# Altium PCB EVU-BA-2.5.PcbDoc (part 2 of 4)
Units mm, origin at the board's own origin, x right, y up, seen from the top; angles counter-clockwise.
Board outline 80 x 82.5 mm, 4 copper layers (Top Layer, Int1, Int2, Bottom Layer), stack 1.49 mm thick; 257 components, 201 nets, 889 pads, 696 vias.
Unrouted connection lines stored in the file: 1.
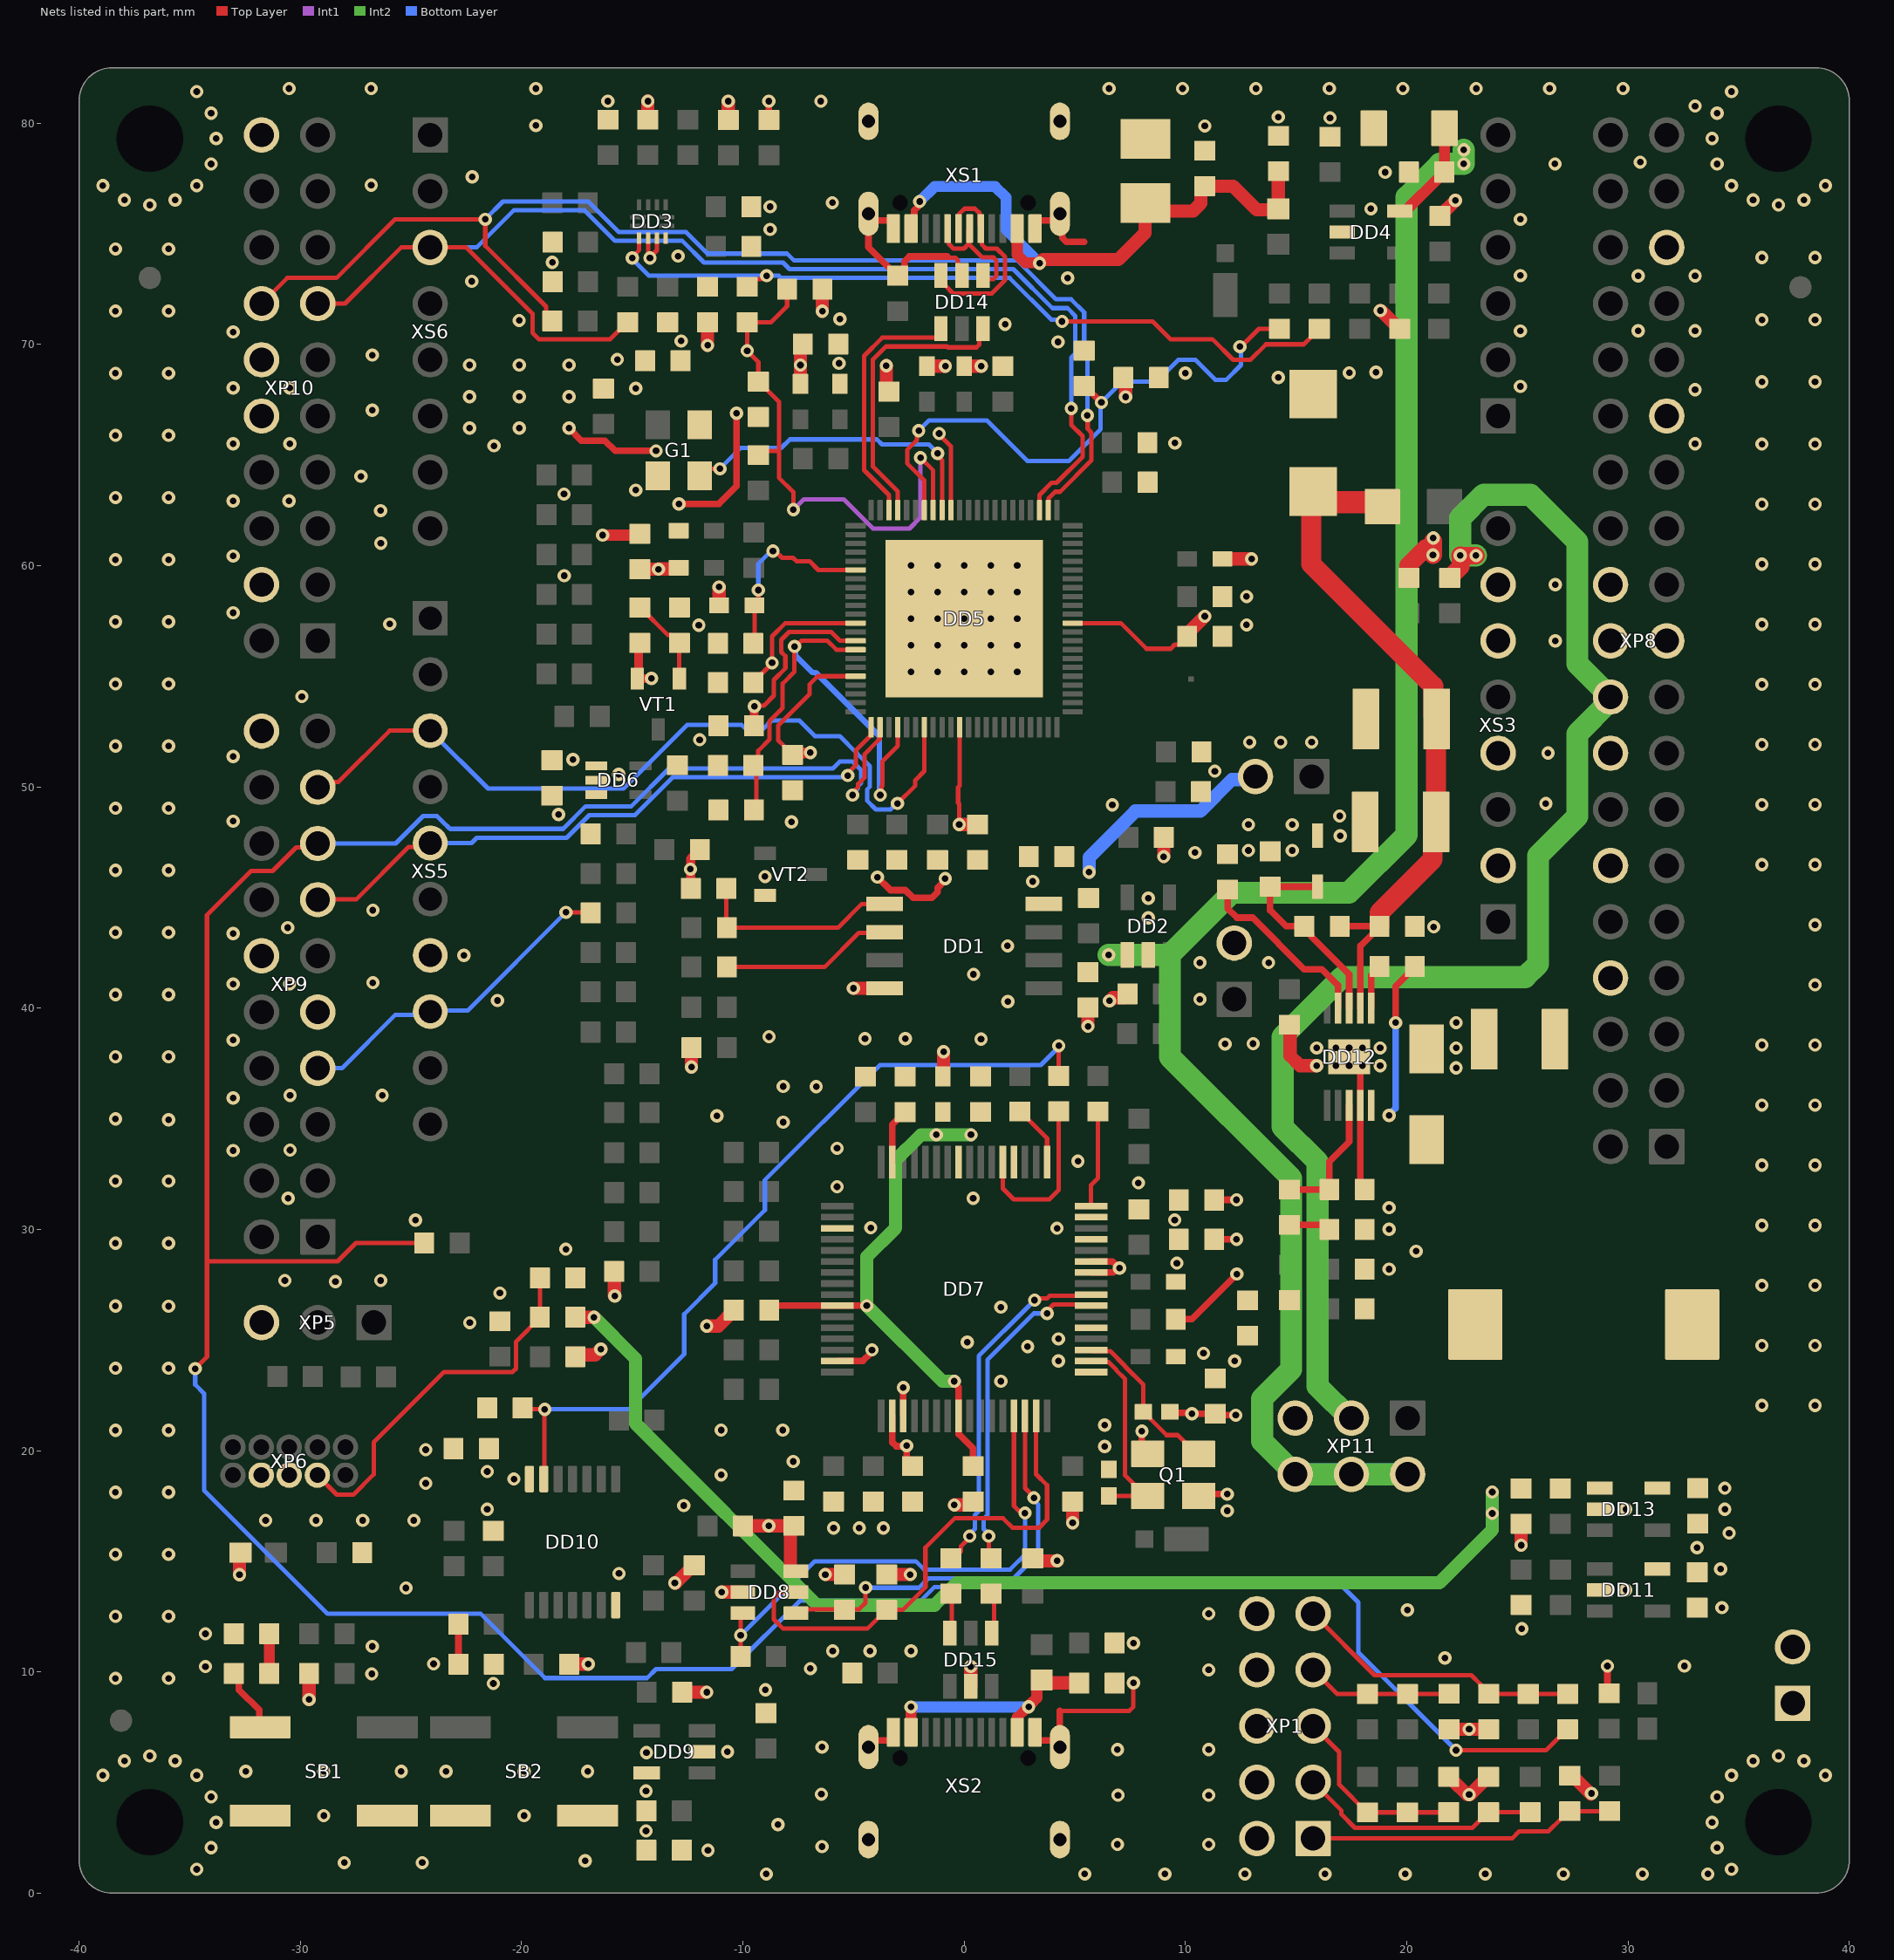
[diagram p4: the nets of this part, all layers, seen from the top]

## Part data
C1 C3 C7 C9 C10 C11 C12 C14 C15 C16 C17 C18 C19 C20 C21 C22 C23 C24 C25 C26 C29 C32 C33 C34 C35 C36 C37 C39 C41 C45 C46 C47 C48 C49 C50 C51 C52 C53 C54 C55 C57 C59 C60 C61 C62 C65 C67 C68 C75: "0603 X7R 0,1 uF ±10% 50V", Manufacturer="\"Kemet\"", Power_Voltage=50V, Tolerance=±10%, Value Ru="0,1 мкФ"
C2 C5 C6 C8 C27 C28 C30 C31 C40 C66 C69 C73 C74: "0603 X7R 1,0 uF±10% 16V", Manufacturer="\"Murata\"", Power_Voltage=16V, Tolerance=±10%, Value Ru="1,0 мкФ"
C4: "10 uF±20% 20V, Tantal capacitor, Type B", Manufacturer="\"Vishay\"", Power_Voltage=20V, Tolerance=±20%, Value Ru=10мкФ
C13: "1206 X7R 10 uF±10% 25V", Manufacturer="\"Murata\"", Power_Voltage=25V, Tolerance=±10%, Value Ru="10 мкФ"
C38: "0603 X7R 470 nF±10% 25V", Manufacturer="\"Murata\"", Power_Voltage=25V, Tolerance=±10%, Value Ru="0,47 мкФ"
C42 C43: "0402 COG 15 pF±5% 50V", Manufacturer="\"Murata\"", Power_Voltage=50V, Tolerance=±5%, Value Ru="15 пФ"
C44 C56 C58: "0603 X5R 4,7 uF ±10% 6,3V", Manufacturer="\"Murata\"", Power_Voltage=6,3V, Tolerance=±10%, Value Ru="4.7 мкФ"
C63 C64: "1210 X7R 2,2 uF±10% 100V", Manufacturer="\"Murata\"", Power_Voltage=100V, Tolerance=±10%, Value Ru="2,2 мкФ"
C70: "0603 X7R 33 nF±10% 50V", Manufacturer="\"Murata\"", Power_Voltage=50V, Tolerance=±10%, Value Ru="33000 пФ"
C71: "0603 X7R 15 pF±10% 16V", Manufacturer="\"Kemet\"", ManufacturerPartNumber=C0603C100K4RAC, Power_Voltage=16V, Tolerance=±10%, Value Ru="15 пФ"
C72: "1210 X7R 47 uF±20% 10V", Manufacturer="\"Murata\"", Power_Voltage=10V, Tolerance=±20%, Value Ru="47 мкФ"
D1: library part SMBJ48A-TR, "TVS Diode (Uni-directional)", Manufacturer="\"STMicroelectronics\"", Manufacturer_Name=STMicroelectronics, Mouser Part Number=511-SMBJ48A-TR, Power_Voltage="Vrm 48V, Irm 0.2A"
D2: "Zener Diode Vstab=4.7V, Iforvard=100mA, SOD-323, 0.55W", Manufacturer="\"Nexperia\"", Mouser Part Number=N/A
D3: "Schottky Diode  60V 3.0A", Arrow Part Number=B360A-E3/61T, Manufacturer="\"Vishay\"", Mouser Part Number=625-B360A-E3/61T
D6 D7: "Schottky Diod", Manufacturer="\"Vishay\""
DD1: "NOR Flash Serial (SPI, Dual SPI, Quad SPI) 3V/3.3V 128M-bit 128M", Arrow Part Number="MT25QL128ABA1ESE-0SIT TR", Manufacturer="\"Micron\"", Mouser Part Number=340-224871-REEL
DD2 DD11 DD13: "LDO voltage regulator Vout -3.3V, Iout - 0.6A max, Vout accuracy ±1.5%", Manufacturer="\"Diodes\"", Manufacturer_Name="Diodes Incorporated", Mouser Part Number=621-AP2112K-3.3TRG1
DD3: "USB Type-C Logic & Port Control", Manufacturer="\"Texas Instruments\"", Mouser Part Number=595-TUSB320RWBR
DD4: "Power switch, USB switch, 1.5A", Manufacturer="\"Diodes Incorporated\"", Mouser Part Number=621-AP2191WG-7
DD5: "Microcontroller BE-U1000", Manufacturer="\"Baikal Electronics\"", Package=None
DD6: "V-Ref Adjustable 0.2V to 18V 15mA", Manufacturer="\"Diodes Incorporated\"", Mouser Part Number=522-ZXRE160H5TA
DD7: "USB-UART/FIFO", Manufacturer="\"FTDI Chip\"", Mouser Part Number=895-FT2232HL
DD8: "EEPROM, 2KBIT, SERIAL, 2MHz", Arrow Part Number=93LC56BT-E/OT, Manufacturer="\"Microchip\"", Mouser Part Number=579-93LC56BT-E/OT
DD9: "Supervisor Integrated Circuit", Manufacturer="\"Texas Instruments\""
DD10: "Quadruple 2-Input Positive-AND Gates, PW0014A, LARGE T&R", F @ Nom Voltage(Max)(Mhz)=100, Generic Part Number=SN74AC08, ICC @ Nom Voltage(Max)(mA)=0.02, Manufacturer="\"Texas Instruments\"", Operating Temperature Range(C)="-40 to 85", Rating=Catalog, tpd @ Nom Voltage(Max)(ns)=10,8.5, Voltage(Nom)(V)=3.3,5
DD12: "DC-DC STEP DOWN Converter 1.5-A, 60V", Manufacturer="\"Texas Instruments\"", Mouser Part Number=595-TPS54160DGQ
DD14 DD15: "Very low capacitance ESD protector", Manufacturer="\"STMicroelectronics\""
FU1: "Fuse SMD 1,5A 63V", Manufacturer="\"Littelfuse\""
G1: "3.3V ±10ppm 5mA ±20ppm CMOS 25MHz  Oscillator", Manufacturer="\"YXC\""
L1 L10: "330 Ohms/100 MHz 1,5A 0,07 Ohms", Manufacturer="\"Murata\"", Value Ru="330 Ом/100MГц 1,5А 0,07 Ом"
L2 L3 L4 L5 L6 L7 L8 L9 L11 L12 L13: "470 Ohms/100MHz 1A 0,2 Ohms", Manufacturer="\"Murata\"", Value Ru="470 Ом/100MГц 1А 0,2 Ом"
L14: "33 uH±30% 2.75A 65mOhm SMD", Manufacturer="\"Sumida\"", Power_Voltage="2,4 A", Value Eng=33uH
LD1: "0603 LED Diod SMD Green", Manufacturer="\"Kingbright\""
LD2: "0603 LED Diod SMD White", Manufacturer="\"Kingbright\""
Q1: "Quartz Crystal 12MHz", Manufacturer="\"YXC\"", Value Ru="12,000 МГц"
R1 R78: "0603 100 Ohm±5% 0,1W", Manufacturer="\"Bourns\"", Power_Voltage=0,1W, Tolerance=±5%, Value Ru="100 Ом"
R2 R4 R6 R9 R10 R11 R12 R14 R17 R30 R32 R35 R38 R59 R62 R63 R80 R81 R82 R86 R107 R108 R112: "0603 10 kOhm±5% 0,1W", Manufacturer="\"Bourns\"", Power_Voltage=0,1W, Tolerance=±5%, Value Ru="10 кОм"
R3 R5 R7 R25 R26 R27 R28 R33 R72 R73 R74 R75 R76: "0603 22 Ohm ±5% 0.1W", Manufacturer="\"Bourns\"", Power_Voltage="0,1 Вт", Tolerance=±5%, Value Ru="22 Ом"
R8 R22 R23 R24 R34 R36 R37 R43 R44 R46 R47 R48 R49 R50 R51 R53 R56 R64 R65 R66 R67 R68 R69 R70 R71 R77 R79 R83 R84 R85 R90 R96 R98 R99 R100 R101 R102 R104 R105 R106 R114 R115 R116 R118 R119: "0603 0 Ohm 0,1W", Manufacturer="\"Bourns\"", Value Ru="0 Ом"
R13 R15 R109 R110: "0603 5,1 kOhm±5% 0,1W", Manufacturer="\"Bourns\"", ManufacturerPartNumber=CR0603-JW-682-E, Power_Voltage="0,1 Вт", Tolerance=±5%, Value Eng=5K1
R16: "0603 887 kOhm ±1% 0,1W", Manufacturer="\"Bourns\"", Power_Voltage="0,1 Вт", Tolerance=±1%, Value Ru="887 кОм"
R18 R19 R20 R21 R42 R111 R113: "0603 100 kOhm±5% 0.1W", Manufacturer="\"Bourns\"", Power_Voltage="0,1 Вт", Tolerance=±5%, Value Ru="100 кОм"
R29 R31: "0603 4,7 kOhm±5% 0.1W", Manufacturer="\"Bourns\"", Power_Voltage="0,1 Вт", Tolerance=±5%, Value Ru="4,7 кОм"
R39 R40 R41: "0603 200 kOhm±5% 0.1W", Manufacturer="\"Bourns\"", Power_Voltage="0,1 Вт", Tolerance=±5%, Value Ru="200 кОм"
R45 R52 R103 R117: "0603 1 kOhm±5% 0,1W", Manufacturer="\"Bourns\"", Power_Voltage="0,1 Вт", Tolerance=±5%, Value Eng=1K
R54: "0603 15 kOhm ±1% 0,1W", Manufacturer="\"Bourns\"", Power_Voltage="0,1 Вт", Tolerance=±1%, Value Ru="15 кОм"
R55 R94 R95: "0603 10 kOhm±1% 0,1W", Manufacturer="\"Bourns\"", Power_Voltage="0,1 Вт", Tolerance=±1%, Value Ru="10 кОм"
R57 R58: "0603 10 Ohm±5% 0.1W", Manufacturer="\"Bourns\"", Power_Voltage=0,1W, Tolerance=±5%, Value Ru="10 Ом"
R60 R97: "0603 2 kOhm±5% 0.1W", Manufacturer="\"Bourns\"", Power_Voltage="0,1 Вт", Tolerance=±5%, Value Ru="2 кОм"
R61: "0603 12 kOhm±1% 0,1W", Manufacturer="\"Bourns\"", ManufacturerPartNumber=CR0603-JW-123-E, Power_Voltage="0,1 Вт", Tolerance=±1%, Value Ru="12 кОм"
R87: "0603 330 Ohm ±5% 0.1W", Manufacturer="\"Bourns\"", Power_Voltage="0,1 Вт", Tolerance=±5%, Value Ru="330 Ом"
R88 R91: "0603 154 kOhm±1% 0,1W", Manufacturer="\"Bourns\"", Power_Voltage="0,1 Вт", Tolerance=±1%, Value Ru="154 кОм"
R89: "0603 22,1 kOhm±1% 0,1W", Manufacturer="\"Bourns\"", Power_Voltage="0,1 Вт", Tolerance=±1%, Value Ru="22,1 кОм"
R92: "0603 88,7 kOhm±1% 0,1W", Manufacturer="\"Bourns\"", Power_Voltage=0,1W, Tolerance=±1%, Value Ru="88,7 кОм"
R93: "0603 53,6 kOhm ±1% 0,1W", Manufacturer="\"Bourns\"", Power_Voltage=0,1W, Tolerance=±1%, Value Ru="53,6 кОм"
SB1 SB2: "Surface-mounting Sealed Tactile Switch", Manufacturer="\"Omron Corporation\"", ManufacturerPartNumber=B3SL-1022P
VT1: "P-MOSFET 50V 130mA SOT-23-3", Manufacturer="\"NXP Semiconductors\""
VT2: "N-MOSFET 50V 200mA SOT-23-3", Manufacturer="\"Fairchild Semiconductor\""
XP1: "Connector 2.54 pitch, 2 rows, 8.54 height, 5 pins per row", Manufacturer="\"Connfly\"", ManufacturerPartNumber=DS1021-2x5
XP2 XP3 XP7: "Connector 2.54 pitch, 1 row, 8.54 height, 2 pins per row", Manufacturer="\"Connfly\""
XP5: "Connector 2.54 pitch, 1 row, 8.54 height, 3 pins per row", Manufacturer="\"Connfly\""
XP6: "Connector 1.27 pitch, 2 rows, 5 pins per row", Manufacturer="\"Samtec\"", Manufacturer_Name=SAMTEC, Mouser Part Number=200-FTSH10501FDK
XP8: "Connector 2.54 pitch, 2 rows, 18.54 height, 19 pins per row", Manufacturer="\"Samtec\""
XP9 XP10: "Connector 2.54 pitch, 2 rows, 18.54 height, 10 pins per row", Manufacturer="\"Samtec\""
XP11: "Connector 2.54 pitch, 2 rows, 8.54 height, 3 pins per row", Manufacturer="\"Connfly\""
XS1 XS2: "USB TYPE-C 5A 16P Female SMD USB Connectors", Manufacturer="\"HRO\"", Package=None
XS3 XS6: "Connector 2.54 pitch, 1 row, 8.54 height, 8 pins per row", Manufacturer="\"Connfly\"", ManufacturerPartNumber="DS-1023-1x8 (PBS-8)"
XS4: "Connector 2.54 pitch, 1 row, 8.54 height, 6 pins per row", Manufacturer="\"Connfly\"", ManufacturerPartNumber=DS1023-1x6S21(PBS-6)
XS5: "Connector 2.54 pitch, 1 row, 8.54 height, 10 pins per row", Manufacturer="\"Connfly\"", ManufacturerPartNumber="DS1023-1X10S21 (PBS-10)"

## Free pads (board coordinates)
  round 1.6 hole 3 paste-2539.97 mask+1: 3(-36.8,3.2) 3(-36.8,79.3) 3(36.8,79.3) 3(36.8,3.2)

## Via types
v1: diameter 0.6, hole 0.3, Top Layer to Bottom Layer, tented both sides, 670 vias
v2: diameter 0.6, hole 0.3, Top Layer to Bottom Layer, tented bottom, 26 vias

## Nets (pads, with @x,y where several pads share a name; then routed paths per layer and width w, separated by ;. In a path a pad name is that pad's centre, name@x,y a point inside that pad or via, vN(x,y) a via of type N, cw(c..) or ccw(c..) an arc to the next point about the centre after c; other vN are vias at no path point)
1V7: C31.1 C37.2 DD5.37 DD5.48 | length 22.7
  Top Layer w0.2: C31.1@-9.528,50.975 C31.1@-9.392,50.975 ; C37.2@-9.392,49.23 C31.1@-9.392,50.975 ; v1(-7.667,56.345) -7.667,55.202 -8.2,54.669 -8.2,53.566 -8.8,52.966 -8.8,52.137 -9.304,51.633 -9.304,51.063 C31.1@-9.392,50.975 ; v1@-7.558,56.4 -7.358,56.6 -6.173,56.6 -5.773,56.2 DD5.37@-4.905,56.2 ; v1(-3.79,49.628) -3.734,49.685 -3.734,50.02 -3.695,50.058 -3.695,51.153 -3.4,51.448 -3,51.848 DD5.48@-3,52.695
  Bottom Layer w0.25: v1(-7.667,56.345) -7.625,56.303 -7.625,55.933 -6.859,55.167 -6.711,55.167 -3.832,52.288 -3.832,49.669 v1(-3.79,49.628)
3V3: C7.1 C10.1 C23.2 C25.2 C29.2 C61.2 C62.2 C74.2 DD3.12 DD5.36 DD6.3 DD9.5 DD10.14 DD13.5 G1.4 L3.1 L4.1 L5.1 L6.1 LD2.1 R2.1 R4.1 R6.1 R14.2 R17.1 R23.1 R29.2 R31.2 R32.2 R35.1 R38.2 R39.1 R40.1 R52.1 R79.2 R80.2 R81.2 R82.2 R86.2 R104.1 R107.2 R111.1 R117.1 R118.2 VT1.2 XP1.2 XP1.4 XP1.6 XP1.8 XP1.10 XP8.12 XP8.16 XP10.10 XS3.2 XS3.4 | length 34.5
  Top Layer w0.2: v1(-9.481,53.637) -9.456,53.662 -9.057,53.662 -8.6,54.119 -8.6,54.834 -8.078,55.356 -8.078,55.908 -8.267,56.097 -8.267,56.649 -7.915,57 -6.007,57 -5.607,56.6 DD5.36@-4.905,56.6
  Top Layer w0.4: R117.1@-15.818,28.099 R117.1@-15.803,28.084 ; v1@-15.803,27.007 v1(-15.788,26.992) ; VT1.2@-14.771,54.69 VT1.2@-14.771,54.89 VT1.2@-14.767,54.894 ; R111.1@-14.658,56.503 -14.715,56.447 -14.715,54.947 VT1.2@-14.767,54.894 ; v1(-14.133,54.899) -14.137,54.894 VT1.2@-14.767,54.894 ; R4.1@-12.348,45.505 -12.358,45.515 -12.358,46.27 v1(-12.368,46.28) -12.356,46.293 -12.356,46.756 R52.1@-11.943,47.168 ; C23.2@-9.5,52.762 -9.49,52.772 -9.49,53.628 v1(-9.481,53.637)
  Top Layer w0.6: LD2.1@-32.801,15.387 -32.75,15.336 v1(-32.75,14.388) ; v1(-29.601,8.75) R14.2@-29.601,9.922 ; R80.2@-17.912,10.347 R80.2@-17.851,10.347 v1(-16.991,10.347) ; R104.1@-17.571,24.246 -17.486,24.331 -16.672,24.331 v1(-16.417,24.586) ; v1@-15.803,27.007 R117.1@-15.803,28.084 ; C25.2@-14.658,59.835 v1(-13.815,59.835) -13.8,59.85 -12.95,59.85 L6.1@-12.9,59.9 ; R32.2@-14.294,80.152 v1(-14.294,80.99) v1@-14.294,81.002 ; v1(-13.075,14.017) -13.025,14.017 -12.375,14.667 -12.35,14.667 R86.2@-12.2,14.817 ; R81.2@-12.746,9.082 v1(-11.634,9.082) ; v1(-12.323,37.334) R2.1@-12.323,38.284 ; L5.1@-11.075,58.2 v1(-11.075,59.033) ; R17.1@-10.659,80.14 v1(-10.659,80.99) ; v1(-6.41,71.5) -6.41,72.325 -6.4,72.335 R40.1@-6.4,72.5 ; L3.1@-1.683,69.012 v1@-0.85,69.012 ; v1(6.571,40.329) 6.712,40.47 7.237,40.47 7.387,40.62 R6.1@7.387,40.645 ; v1(9.019,46.845) R23.1@9.019,47.72 ; L4.1@11.675,60.3 v1(12.986,60.3) ; R38.2@21.5,75.8 v1(22.201,76.501)
  Top Layer w0.8: R118.2@20.073,59.5 20.073,60.01 20.856,60.793 21.193,60.793 ; v1@21.193,60.478 21.193,60.793 ; v1@21.193,61.107 21.193,60.793
  Int1 w0.4: v1(-14.133,54.899) v1@-14.116,54.899
  Int2 w0.4: v1(-16.417,24.586) v1@-16.372,24.586
  other v1: -14.377,2.812 -14.377,4.612 -14.355,6.35 -21.55,17.35 34.375,17.35 34.375,18.3 -20.347,18.717 -21.55,19.054 -17.68,51.231 21.184,60.478 21.199,61.246 -14.843,68.01 -0.85,69.012 -12.791,70.15 -18.61,73.705 -12.925,73.986
3V3_FTDI: C46.2 C54.1 C55.2 C56.2 C57.2 C58.2 C69.2 DD7.50 DD8.6 DD11.5 L11.1 L12.2 L13.2 R59.1 R62.1 R63.1 | length 10.8
  Top Layer w0.3: DD7.50@-3.25,21.562 -3.25,20.375 -3.074,20.199 v1@-2.6,20.199 ; v1(-2.6,20.221) v1@-2.6,20.199 ; C46.2@-2.325,19.3 -2.6,19.575 v1@-2.6,20.199
  Top Layer w0.6: R59.1@-10,16.596 v1(-8.825,16.596) -8.823,16.598 C54.1@-7.707,16.598 ; DD8.6@-7.6,14.55 -7.85,14.55 -7.855,14.555 -7.855,16.45 C54.1@-7.707,16.598 ; v1(-6.275,14.4) R62.1@-5.4,14.4 ; R63.1@-3.5,14.4 v1(-2.436,14.4) ; L11.1@-0.962,36.782 -0.93,36.814 v1(-0.93,38.029) ; C54.1@-7.707,16.598 -7.702,16.598 C54.1@-7.7,16.6 -7.705,16.6 C54.1@-7.707,16.598
  other v1: 34.18,14.65 33.124,15.618 12.226,24.05 10.817,24.4 9.614,28.472 9.514,30.425
3V3_QSPI: C6.1 DD1.8 R24.2 XP2.2 | length 9.7
  Bottom Layer w0.6: v1(5.646,46.15) 5.646,46.816 7.735,48.905 10.676,48.905 12.098,50.328 13.024,50.328 XP2.2@13.163,50.467
5V: C2.1 C11.1 C13.2 C73.2 DD2.1 DD4.5 DD13.1 R96.1 R99.2 XP11.2 XP11.4 XP11.6 | length 141.9
  Top Layer w0.5: DD4.5@19.682,76.025 19.957,76.025 20.007,76.075 20.007,76.091 21.476,77.56 21.501,77.56 21.701,77.76 C11.1@21.701,77.785 21.704,77.788 21.704,79.763 C13.2@21.707,79.766
  Top Layer w0.6: R99.2@-17.576,26.026 v1(-16.726,26.026)
  Int2 w0.6: v1(-16.726,26.026) -14.85,24.15 -14.85,21.225 -6.638,13.013 -1.34,13.013 -0.328,14.025 21.475,14.025 23.863,16.413 v1(23.863,17.163) v1(23.863,18.13)
  Int2 w1: v1(6.525,42.405) 9.298,42.405 ; XP11.2@20.04,18.93 XP11.4@17.5,18.93 XP11.6@14.96,18.93 13.46,20.43 13.46,22.348 14.777,23.665 14.777,32.313 9.298,37.791 9.298,42.405 ; v1(22.58,78.788) v1(22.58,78.154) 21.492,78.154 19.998,76.659 19.998,47.824 17.383,45.21 12.103,45.21 9.298,42.405
  Bottom Layer w1: XP11.6@14.96,18.93 XP11.4@17.5,18.93 XP11.2@20.04,18.93
5V_EXT: R115.2 XP8.18 XP11.3 | length 63.3
  Top Layer w0.8: R115.2@21.992,59.5 22.437,59.946 22.437,60.277 22.437,60.457 v1(22.417,60.458) ; v1@22.595,60.453 v1(23.131,60.453)
  Int2 w0.2: v1(22.417,60.458) v1@22.419,60.455 ; v1@23.128,60.455 v1(23.131,60.453)
  Int2 w1: XP11.3@17.51,21.373 15.977,22.906 15.977,33.045 14.389,34.633 14.389,38.702 17.087,41.4 25.348,41.4 25.933,41.986 25.933,46.887 27.71,48.663 27.71,52.397 29.21,53.898 XP8.18@29.21,54.06 27.71,55.56 27.71,59.761 27.71,61.079 25.585,63.204 23.474,63.204 22.417,62.147 v1(22.417,60.458) ; v1@22.419,60.455 v1@23.128,60.455
5V_INT: C72.2 L14.2 R93.2 R95.2 XP11.5 | length 0.1
  Top Layer w0.3: R95.2@14.7,26.8 R95.2@14.725,26.8 ; R93.2@18.1,26.4 18.1,26.375 R93.2@18.149,26.326
AREF: R46.2 XP9.7 XS5.8 | length 15.2
  Top Layer w0.2: v1(-17.991,44.33) -16.95,44.33 R46.2@-16.925,44.355
  Bottom Layer w0.2: XP9.7@-29.21,37.29 -28.11,37.29 -25.7,39.7 -24.27,39.7 -24.087,39.883 -22.438,39.883 v1(-17.991,44.33)
CLK_25MHz: DD5.14 G1.3 | length 14.3
  Top Layer w0.2: G1.3@-11.95,64.06 -11.633,64.377 v1(-11.036,64.377) ; v1(-1.2,65.074) -1.2,64.966 -1,64.766 DD5.14@-1,62.505
  Bottom Layer w0.2: v1(-11.036,64.377) -11.036,64.384 -10.346,65.074 -10.105,65.315 -8.262,65.315 -7.874,65.703 -3.942,65.703 -3.711,65.472 -1.597,65.472 v1(-1.2,65.074)
CLK_STRAP: R108.2 R113.1 XP1.1 | length 13.9
  Top Layer w0.2: XP1.1@15.77,2.47 16.1,2.47 24.761,2.47 25.091,2.8 26.412,2.8 26.967,3.356 26.99,3.356 27.317,3.683 27.317,3.706 R108.2@29.165,3.706
CS_1/PA8: DD5.51 XP9.17 XS5.3 | length 36.6
  Top Layer w0.2: XP9.17@-29.21,49.99 -28.982,50.218 -28.282,50.218 -25.96,52.54 XS5.3@-24.13,52.54 ; v1(-3.009,49.25) -2.209,50.05 -2.209,50.301 -1.8,50.71 DD5.51@-1.8,52.695
  Bottom Layer w0.2: XS5.3@-24.13,52.54 -21.513,49.923 -15.396,49.923 -12.524,52.795 -10.053,52.795 -9.895,52.637 -9.064,52.637 -8.703,52.998 -7.446,52.998 -6.745,52.297 -5.627,52.297 -4.842,51.512 -4.257,50.926 -4.257,50.01 -4.39,49.876 -4.39,49.379 -3.992,48.981 -3.326,48.981 -3.057,49.25 v1(-3.009,49.25)
DBG_SEL: R12.2 R19.1 XP1.3 | length 11.1
  Top Layer w0.2: XP1.3@15.77,5.01 17.05,3.73 17.05,3.56 17.66,2.95 22.966,2.95 R19.1@23.684,3.668 ; R19.1@23.697,3.656 R12.2@25.586,3.656
DTR_RST: C75.1 DD10.13 R107.1 | length 38
  Top Layer w0.2: R107.1@-19.95,21.925 -19.89,21.865 v1@-19.097,21.865 ; DD10.13@-18.997,18.717 -18.976,18.738 -18.976,21.844 v1(-18.955,21.865) ; C75.1@4.276,36.934 v1(4.276,38.298)
  Bottom Layer w0.2: v1(-18.955,21.865) -15.143,21.865 -12.653,24.355 -12.653,26.164 -11.251,27.566 -11.251,28.624 -9.004,30.871 -9.004,32.229 -3.803,37.429 3.467,37.429 4.276,38.238 v1(4.276,38.298)
ECLK: DD7.62 DD8.4 R62.2 | length 18.9
  Top Layer w0.2: DD8.4@-7.6,12.65 -7.417,12.833 R62.2@-5.433,12.833 ; R62.2@-5.367,12.833 -4.742,12.833 -4.462,13.113 -4.462,13.801 v1(-4.45,13.813) ; DD7.62@2.75,21.562 2.75,18.508 2.75,18.306 3.15,17.906 v1(3.15,17.869)
  Bottom Layer w0.2: v1(-4.45,13.813) -4.437,13.8 -2.051,13.8 -1.627,14.224 2.24,14.224 3.35,15.334 3.35,17.561 3.15,17.761 v1(3.15,17.869)
ECS: DD7.63 DD8.5 R63.2 | length 22.9
  Top Layer w0.2: DD8.5@-7.6,13.6 -8.355,13.6 -8.6,13.355 -8.6,12.372 -8.178,11.95 -4.375,11.95 -3.525,12.8 -2.775,12.8 -1.751,13.824 -1.751,15.614 -0.425,16.94 1.762,16.94 2.189,16.512 3.38,16.512 3.75,16.882 3.75,18.433 3.25,18.933 DD7.63@3.25,21.562
EDATA: DD7.61 DD8.3 R60.1 | length 23.5
  Top Layer w0.2: R60.1@-10.1,10.7 v1(-10.1,11.65) -10.1,12.55 DD8.3@-10,12.65 DD8.3@-9.795,12.855 ; DD7.61@2.25,21.562 2.25,17.5 2.497,17.253 2.673,17.253 v1(2.75,17.177)
  Bottom Layer w0.2: v1(-10.1,11.65) -6.75,15 -2.187,15 -1.811,14.624 2.074,14.624 2.75,15.3 v1(2.75,17.177)
FT_N: DD7.7 R57.2 | length 15
  Top Layer w0.2: R57.2@1.111,15.089 v1(1.111,16.134) ; v1(3.75,26.2) 3.75,26.308 3.916,26.474 3.916,26.483 4.033,26.6 5.688,26.6 DD7.7@5.738,26.55
  Bottom Layer w0.2: v1(1.111,16.134) 1.111,16.221 0.88,16.452 0.88,16.92 1.058,17.097 1.058,24.108 3.15,26.2 v1(3.75,26.2)
FT_P: DD7.8 R58.2 | length 16
  Top Layer w0.2: R58.2@-0.605,15.009 -0.58,15.009 -0.141,15.447 -0.141,15.677 0.25,16.068 v1(0.25,16.134) ; v1(3.184,26.8) 3.259,26.874 3.261,26.872 3.739,26.872 3.867,27 5,27 5.688,27 DD7.8@5.738,27.05
  Bottom Layer w0.2: v1(0.25,16.134) 0.25,16.221 0.48,16.452 0.48,17.086 0.658,17.263 0.658,24.274 2.867,26.483 v1(3.184,26.8)
FT_USB_N: DD15.4 R57.1 | length 1.7
  Top Layer w0.2: R57.1@1.3,13.3 1.35,13.25 DD15.4@1.35,11.6
FT_USB_P: DD15.6 R58.1 | length 1.7
  Top Layer w0.2: DD15.6@-0.55,11.6 -0.55,13.25 R58.1@-0.5,13.3
FTDI_RX: DD7.17 R70.1 | length 2.8
  Top Layer w0.2: R70.1@2.523,35.34 2.523,35.339 2.885,34.977 2.887,34.977 3.75,34.114 DD7.17@3.75,33.038
FTDI_TX: DD7.16 R71.1 | length 4.4
  Top Layer w0.2: DD7.16@5.738,31.05 5.738,32.008 6.05,32.32 R71.1@6.05,35.327
FTDI_VCCIO: C45.2 C48.2 C51.2 C53.2 DD7.20 DD7.31 DD7.42 DD7.56 L11.2 | length 27.6
  Top Layer w0.3: C51.2@-8.811,26.349 -8.61,26.55 DD7.42@-5.738,26.55 v1(-4.4,26.55) ; DD7.31@-3.25,33.038 -3.25,34.739 -2.687,35.302 C48.2@-2.662,35.302 ; v1(-0.445,23.133) -0.445,23.052 -0.25,22.857 DD7.56@-0.25,21.562 -0.25,20.75 0.4,20.1 C53.2@0.4,19.3
  Int2 w0.6: v1(-0.445,23.133) -0.983,23.133 v1(-4.4,26.55) -4.4,28.761 -3.1,30.061 -3.1,33.125 -1.95,34.276 v1(0.309,34.276)
  other v1: -1.256,34.276
GND: C2.2 C3.2 C4.2 C5.1 C6.2 C7.2 C8.1 C9.2 C10.2 C11.2 C12.1 C13.1 C14.2 C15.2 C16.1 C17.2 C18.2 C19.2 C20.2 C21.2 C22.2 C23.1 C24.2 C25.1 C26.1 C29.1 C30.2 C31.2 C32.1 C33.1 C34.1 C35.1 C36.1 C37.1 C38.2 C39.2 C40.2 C41.2 C42.1 C43.1 C44.1 C45.1 C46.1 C47.2 C48.1 C49.1 C50.2 C51.1 C52.2 C53.1 C54.2 C55.1 C56.1 C57.1 C58.1 C59.1 C61.1 C62.1 C63.1 C64.1 C65.1 C66.1 C67.1 C69.1 C70.1 C71.1 C72.1 C73.1 C74.1 D1.2 D2.2 D3.2 DD1.4 DD2.2 DD3.10 DD3.11 DD4.2 DD5.89 DD6.1 DD6.2 DD7.1 DD7.5 DD7.10 DD7.11 DD7.13 DD7.15 DD7.25 DD7.35 DD7.47 DD7.51 DD8.2 DD9.2 DD10.7 DD11.2 DD12.9 DD12.11 DD13.2 DD14.2 DD15.2 G1.2 L7.1 L9.1 pad.3 Q1.2 Q1.4 R1.1 R13.1 R15.1 R18.2 R19.2 R20.2 R21.2 R30.2 R41.1 R42.2 R54.1 R61.1 R77.1 R78.1 R87.1 R89.1 R91.1 R94.1 R97.2 R98.2 R109.2 R110.2 R112.1 R113.2 SB1.3 SB1.4 SB2.3 SB2.4 VT2.2 XP3.2 XP5.3 XP6.3 XP6.5 XP7.1 XP7.2 XP8.8 XP8.19 XP8.20 XP8.22 XP8.27 XP8.33 XP9.9 XP9.12 XP9.20 XP10.4 XP10.12 XP10.20 XS1.A1_B12 XS1.B1_A12 XS1.S1 XS1.S2 XS1.S3 XS1.S4 XS2.A1_B12 XS2.B1_A12 XS2.S1 XS2.S2 XS2.S3 XS2.S4 XS3.6 XS3.7 XS5.7 | length 85.1
  Top Layer w0.2: DD3.10@-14.286,74.802 -14.286,73.986 v1(-14.2,73.9) -14.2,73.938 -13.886,74.252 DD3.11@-13.886,74.802 ; C7.2@-11.6,71 C7.2@-11.593,70.993 ; C14.2@-3.453,67.914 C14.2@-3.4,67.862 ; -0.767,73.921 -0.405,73.921 -0.288,73.803 -0.288,73.298 DD14.2@-0.1,73.111 ; 4.325,8.238 7.469,8.238 7.65,8.419 v1(7.65,9.5) ; C52.2@7.875,30.875 C52.2@7.9,30.85
  Top Layer w0.3: v1(-17.86,66.211) -17.299,65.65 -16.237,65.65 -15.77,65.184 v1(-13.924,65.184) ; v1(-12.887,62.789) -11.086,62.789 -10.282,63.592 v1(-10.282,66.887) ; R112.1@-8.823,80.14 v1(-8.823,80.99) ; DD7.47@-5.738,24.05 -4.58,24.05 -4.224,24.406 -4.224,24.493 v1(-4.166,24.55) ; XS2.S1@-4.325,6.6 -4.325,6.63 -4.048,6.907 -3.35,6.907 -3.2,7.057 XS2.A1_B12@-3.2,7.27 ; XS1.S3@-4.325,75.9 -4.325,74.4 -3.025,73.1 C9.2@-3,73.1 -2.703,73.397 -2.703,73.752 -2.484,73.971 -0.767,73.971 ; XS1.S3@-4.048,75.593 -3.35,75.593 -3.2,75.443 XS1.B1_A12@-3.2,75.23 ; v1(-3.92,45.919) -3.33,45.33 -2.651,45.33 -2.305,44.984 -1.455,44.984 -1.197,45.242 -1.197,45.429 -0.857,45.769 v1(-0.857,45.85) ; DD7.51@-2.75,21.562 v1(-2.75,22.85) ; XS2.B1_A12@3.2,7.27 3.2,7.057 3.35,6.907 XS2.S3@4.048,6.907 ; XS1.A1_B12@3.2,75.23 3.2,75.443 3.35,75.593 XS1.S1@4.048,75.593 ; XS2.S3@4.325,6.6 4.325,8.238 ; XS1.S1@4.325,75.9 4.44,75.785 4.44,74.804 4.619,74.625 5.423,74.625 ; DD7.10@5.738,28.05 6.744,28.05 6.944,28.25 v1(7.025,28.25) 6.999,28.25 6.699,28.55 DD7.11@5.738,28.55 ; v1(8.032,20.875) 8.032,20.117 Q1.4@8.299,19.85 ; C43.1@9.349,21.75 9.392,21.707 10.251,21.707 v1(10.293,21.665) 10.935,21.665 11,21.6 v1(12.275,21.6) ; R61.1@9.567,25.94 9.572,25.945 10.291,25.945 v1(12.325,27.979) ; Q1.2@10.681,18.032 v1(11.892,18.032) ; C55.1@11.3,29.55 11.304,29.554 v1(12.31,29.554) ; C56.1@11.3,31.325 11.311,31.336 v1(12.31,31.336) ; v1(18,37.4) 17.9,37.3 DD12.9@17.9,35.6 17.9,32 C71.1@18.1,31.8 ; R42.2@19.682,70.664 19.7,70.682 R42.2@19.682,70.7 ; v1(29.068,10.262) 29.068,9.112 R87.1@29.148,9.033
  Top Layer w0.5: v1(-16.339,61.376) -14.717,61.376 C25.1@-14.658,61.435
  Top Layer w0.6: v1(-11.633,25.629) -11.107,25.629 -10.411,26.324 C51.1@-10.411,26.349 ; v1(-11.593,69.955) C7.2@-11.593,70.993 ; v1(-10.957,13.603) -10.003,13.603 DD8.2@-10,13.6 ; v1(-5,40.895) DD1.4@-3.6,40.895 ; v1(-3.518,69.037) -3.518,67.979 C14.2@-3.453,67.914 ; v1(-0.445,17.539) -0.435,17.55 0.225,17.55 0.375,17.7 C53.1@0.4,17.7 ; DD15.2@0.3,9.339 v1(0.3,10.24) ; R110.2@3.1,15.009 3.108,15.017 4.192,15.017 v1(4.2,15.025) ; v1(4.9,16.734) C47.2@4.9,17.7 ; v1(5.596,39.176) C2.2@5.596,40.026 ; R91.1@14.7,39.252 14.7,39.129 14.727,39.102 14.727,37.848 15.175,37.4 v1(15.929,37.4) ; v1(18.806,71.526) 18.831,71.526 19.682,70.675 R42.2@19.682,70.664 ; R20.2@21.9,5.256 22.05,5.106 22.075,5.106 22.731,4.45 v1(22.821,4.45) 22.866,4.45 23.672,5.256 R19.2@23.697,5.256 ; R21.2@21.917,7.403 R18.2@23.62,7.403 ; v1(25.17,15.724) C73.1@25.17,16.69 ; R113.2@27.46,5.336 27.46,5.236 27.54,5.156 27.64,5.156 v1@28.318,4.478
  other v1: -8.941,0.864 5.45,0.864 9.07,0.864 12.69,0.864 16.31,0.864 19.93,0.864 23.55,0.864 27.077,0.864 30.65,0.864 33.606,0.864 -34.679,1.079 34.679,1.079 -28.013,1.375 -24.488,1.375 -17.122,1.462 -11.575,1.937 -34.028,2.052 34.028,2.052 -6.426,2.1 6.928,2.199 11.05,2.199 -8.411,3.1 -33.8,3.2 33.8,3.2 -28.938,3.5 -19.889,3.5 -34.028,4.348 34.028,4.348 6.95,4.425 11.05,4.425 -6.452,4.47 28.346,4.506 -38.921,5.321 -34.679,5.321 34.679,5.321 38.921,5.321 -32.463,5.5 -28.938,5.5 -25.438,5.5 -23.414,5.5 -19.889,5.5 -17.014,5.5 -37.948,5.972 -35.652,5.972 35.652,5.972 37.948,5.972 -36.8,6.2 36.8,6.2 -10.693,6.387 6.928,6.485 11.05,6.485 -6.426,6.6 22.821,7.409 -8.98,9.19 -21.275,9.472 -38.35,9.709 -35.95,9.709 -26.772,9.906 11.05,10.09 -6.95,10.15 -34.284,10.24 32.55,10.262 -23.978,10.363 21.725,10.627 -5.939,10.94 -4.258,10.94 -2.4,10.94 -26.746,11.151 7.65,11.3 -34.284,11.722 25.2,11.95 -38.35,12.511 -35.95,12.511 11.05,12.63 20.033,12.794 34.239,12.9 29.9,13.7 -25.222,13.792 -15.597,14.446 -38.35,15.314 -35.95,15.314 34.57,16.272 -5.9,16.5 -4.742,16.5 -3.65,16.5 -31.566,16.848 -29.292,16.848 -27.177,16.848 -24.867,16.848 11.892,17.282 29.9,17.35 -12.675,17.518 -38.35,18.117 -35.95,18.117 -24.332,18.523 -10.981,18.9 -7.722,19.507 -24.332,20.041 6.354,20.187 -38.35,20.92 -35.95,20.92 -10.981,20.925 -8.2,20.925 6.354,21.15 36.05,22.037 38.45,22.037 1.658,23.133 -38.35,23.722 -35.95,23.722 4.261,24.05 2.867,24.705 36.05,24.753 38.45,24.753 0.144,24.897 4.261,25.05 -22.341,25.78 1.658,26.483 -38.35,26.531 -35.95,26.525 -20.979,27.121 36.05,27.469 38.45,27.469 -28.41,27.636 -30.698,27.69 -26.364,27.69 19.2,28.2 20.425,29.014 -17.999,29.103 -38.35,29.372 -35.95,29.372 19.2,30 4.195,30.05 -4.222,30.071 36.05,30.185 38.45,30.185 -24.79,30.42 19.2,30.975 -30.551,31.4 0.408,31.4 -5.74,31.928 7.875,32.101 -38.35,32.181 -35.95,32.181 36.05,32.901 38.45,32.901 5.143,33.077 -33.03,33.563 -30.459,33.583 -5.74,33.665 -8.177,34.845 -35.95,34.95 -38.35,34.99 -11.173,35.133 36.05,35.617 38.45,35.617 -33.03,35.942 -30.459,36.059 -26.297,36.059 -6.684,36.452 -8.177,36.459 22.232,37.3 16.8,37.4 17.4,37.4 18.8,37.4 -38.35,37.798 -35.95,37.798 15.929,38.2 16.8,38.2 17.4,38.2 18,38.2 18.8,38.2 22.232,38.2 36.05,38.333 38.45,38.333 11.795,38.377 13.06,38.393 -33.03,38.552 0.763,38.602 -4.479,38.623 -2.658,38.623 -8.818,38.709 22.232,39.341 1.975,40.295 -21.09,40.344 10.655,40.4 -38.35,40.607 -35.95,40.607 38.45,41.049 -33.03,41.09 -30.48,41.09 -26.721,41.148 0.425,41.525 10.655,42.054 13.755,42.054 -22.61,42.38 1.961,42.812 -33.03,43.369 -38.35,43.416 -35.95,43.416 -30.572,43.637 21.218,43.67 38.45,43.765 8.325,44.08 -26.721,44.422 8.325,44.964 3.1,45.726 -8.998,45.944 -38.35,46.224 -35.95,46.224 36.05,46.481 38.45,46.481 10.43,47.028 12.845,47.123 14.824,47.123 16.996,47.786 12.845,48.291 14.824,48.291 -7.8,48.418 -33.03,48.449 16.969,48.681 -18.325,48.75 -38.35,49.033 -35.95,49.033 6.696,49.18 36.05,49.197 38.45,49.197 26.286,49.241 -15.606,50.562 11.326,50.707 -33.03,51.375 26.386,51.527 -38.35,51.842 -35.95,51.842 36.05,51.913 38.45,51.913 12.902,52.017 14.303,52.017 15.703,52.017 -11.95,52.127 -29.928,54.08 36.05,54.629 38.45,54.629 -38.35,54.65 -35.95,54.65 26.71,56.6 -11.991,57.305 12.762,57.319 36.05,57.345 38.45,57.345 -25.96,57.36 -38.35,57.459 -35.95,57.459 -33.03,57.867 12.762,58.6 26.71,59.14 -18.069,59.541 36.05,60.061 38.45,60.061 -38.35,60.268 -35.95,60.268 -33.03,60.433 -26.363,61.012 -26.368,62.485 36.05,62.777 38.45,62.777 -33.03,62.92 -30.507,62.92 -38.35,63.076 -35.95,63.076 -18.083,63.231 -14.843,63.41 -27.254,64.033 -21.25,65.412 -33.03,65.51 -30.472,65.51 33.03,65.502 36.05,65.493 38.45,65.493 9.525,65.54 -38.35,65.885 -35.95,65.885 -22.352,66.211 -20.106,66.211 -26.746,67.021 -22.352,67.636 -20.106,67.636 -17.86,67.634 33.03,67.95 -33.03,68.03 -30.472,68.03 25.135,68.096 36.05,68.302 38.45,68.302 14.2,68.5 -38.35,68.694 -35.95,68.694 10,68.696 17.404,68.713 18.615,68.734 -22.352,69.062 -20.106,69.062 -17.86,69.062 -5.652,69.142 -15.675,69.318 -26.746,69.512 4.238,70.108 -33.03,70.556 25.135,70.606 30.455,70.612 33.03,70.612 1.85,70.905 -20.107,71.077 36.05,71.11 38.45,71.11 -5.615,71.139 -38.35,71.502 -35.95,71.502 -22.25,72.849 4.672,73 30.455,73.097 33.03,73.097 25.135,73.11 36.05,73.919 38.45,73.919 -38.35,74.311 -35.95,74.311 -8.768,75.193 25.139,75.65 18.382,76.125 -8.768,76.219 -36.8,76.3 36.8,76.3 -5.957,76.4 -37.948,76.528 -35.652,76.528 35.652,76.528 37.948,76.528 -38.921,77.179 -34.679,77.179 -26.796,77.191 34.679,77.179 38.921,77.179 -22.234,77.57 19.025,77.775 -34.028,78.152 26.7,78.154 34.028,78.152 30.55,78.232 -33.8,79.3 33.8,79.3 10.875,79.868 -19.355,79.89 16.531,80.235 14.2,80.275 -34.028,80.448 34.028,80.448 33.03,80.77 -16.1,80.99 -6.477,80.99 -34.679,81.421 34.679,81.421 -30.505,81.559 -26.8,81.559 -19.355,81.559 6.55,81.559 9.868,81.559 13.186,81.559 16.504,81.559 19.822,81.559 23.14,81.559 26.458,81.559 29.776,81.559
  other v2: -2.4,55.2 -1.2,55.2 0,55.2 1.2,55.2 2.4,55.2 -2.4,56.4 -1.2,56.4 0,56.4 1.2,56.4 2.4,56.4 -2.4,57.6 -1.2,57.6 0,57.6 1.2,57.6 2.4,57.6 -2.4,58.8 -1.2,58.8 0,58.8 1.2,58.8 2.4,58.8 -2.4,60 -1.2,60 0,60 1.2,60 2.4,60
I2C2_SCL/PB8: DD5.3 R33.2 XP10.13 XS6.3 | length 59.4
  Top Layer w0.2: XP10.13@-29.21,71.84 -27.98,71.84 -25.44,74.38 XS6.3@-24.13,74.38 -22.495,74.38 -19.507,71.392 -19.507,70.519 -19.221,70.233 -15.992,70.233 -15.225,71 R33.2@-15.2,71 ; DD5.3@3.4,62.505 3.4,63.187 3.951,63.738 4.172,63.738 5.353,64.919 5.353,65.847 4.838,66.362 v1(4.838,67.105)
  Bottom Layer w0.2: XS6.3@-24.13,74.38 -22.029,74.38 -20.356,76.053 -17.153,76.053 -15.776,74.676 -12.735,74.676 -11.759,73.7 -8.188,73.7 -7.888,73.4 2.224,73.4 3.989,71.635 4.672,71.635 5.023,71.284 5.023,69.585 4.838,69.4 v1(4.838,67.105)
I2C2_SDA/PB9: DD5.2 R28.2 XP10.14 | length 57
  Top Layer w0.2: XP10.14@-31.75,71.84 -30.59,73 -28.364,73 -25.712,75.652 v1(-21.64,75.652) -21.64,74.453 -18.891,71.705 -18.891,71.335 R28.2@-18.608,71.052 ; DD5.2@3.8,62.505 3.8,62.845 3.82,62.865 3.82,63.041 4.117,63.338 4.338,63.338 5.753,64.753 5.753,66.012 5.583,66.183 5.583,66.77 v1(5.57,66.783)
  Bottom Layer w0.2: v1(-21.64,75.652) -20.839,76.453 -16.988,76.453 -15.611,75.076 -12.569,75.076 -11.593,74.1 -8.002,74.1 -7.702,73.8 2.39,73.8 4.155,72.035 4.838,72.035 5.423,71.449 5.423,69.577 5.57,69.431 v1(5.57,66.783)
ID: DD3.9 R37.1 R44.2 | length 35.7
  Top Layer w0.2: v1(-15,73.9) -15,73.949 -14.686,74.262 DD3.9@-14.686,74.802 ; R37.1@-9.8,72.6 -9.45,72.95 -9.187,72.95 -9.037,73.1 v1(-8.929,73.1) ; v1(4.423,71.035) 8.515,71.035 9.316,70.234 11.215,70.234 12.153,69.296 12.935,69.296 13.639,70 15.35,70 15.675,70.325 15.675,70.35 16.025,70.7 R44.2@16.05,70.7
  Bottom Layer w0.2: v1(-15,73.9) -15,73.851 -14.249,73.1 -8.372,73.1 -8.272,73 2.059,73 3.947,71.112 4.347,71.112 v1(4.423,71.035)
ID_MCU: DD5.15 R37.2 R40.2 R41.2 R114.2 | length 25.2
  Top Layer w0.2: R114.2@-9.3,64.994 -9.117,65.177 -8.371,65.177 ; R41.2@-9.275,68.313 R41.2@-9.3,68.313 -9.3,69.204 v1(-9.804,69.709) -9.804,70.996 -8.727,70.996 -8,71.722 R40.2@-8,72.5 ; R41.2@-9.238,68.276 -8.371,67.41 -8.371,65.177 ; v1(-7.717,62.525) -7.717,63.317 -8.371,63.971 -8.371,65.177 ; v1(-1.974,64.872) -1.4,64.298 DD5.15@-1.4,62.505
  Int1 w0.2: v1(-7.717,62.525) -7.242,63 -5.449,63 -4.12,61.671 -2.473,61.671 -1.974,62.17 v1(-1.974,64.872)
LDO_OUT_1P1: C26.2 C30.1 C33.2 C34.2 C35.2 C36.2 DD5.13 DD5.34 DD5.40 DD5.55 DD5.77 L2.1 L8.1 | length 33.9
  Top Layer w0.2: C30.1@-9.825,54.713 -9.55,54.713 -8.678,55.585 v1(-8.678,55.605) ; v1@-8.683,55.6 v1(-8.678,55.605) ; C33.2@-7.773,51.448 -8.123,51.798 -8.123,51.823 -8.4,52.1 -8.4,52.772 -6.989,54.182 -6.989,54.627 -6.616,55 DD5.40@-4.905,55 ; L8.1@-7.4,68.212 L8.1@-7.392,68.22 ; C26.2@-7.392,69.911 C26.2@-7.289,70.014 ; DD5.34@-4.905,57.4 -8.081,57.4 -8.678,56.803 v1(-8.678,55.605) ; v1(-1.13,65.968) -1.13,65.919 -0.6,65.389 DD5.13@-0.6,62.505 ; v1(-0.225,48.3) -0.225,49.235 -0.273,49.284 -0.273,49.974 -0.2,50.048 -0.2,51.935 -0.2,52.335 DD5.55@-0.2,52.695 ; C35.2@0.176,48.3 C35.2@0.6,48.3 C35.2@0.575,48.3 ; DD5.77@4.905,57.4 7.084,57.4 8.244,56.24 9.333,56.24 9.518,56.425 9.725,56.425 10.075,56.775 C36.2@10.075,56.8 ; C34.2@7.194,68.5 C34.2@7.305,68.389
  Top Layer w0.5: C33.2@-7.773,51.448 -7.687,51.533 -6.969,51.533 v1(-6.95,51.552)
  Top Layer w0.6: L8.1@-7.392,68.22 -7.4,68.228 -7.4,69.903 C26.2@-7.392,69.911 ; v1(-0.225,48.3) 0.176,48.3 C35.2@0.575,48.3 ; L2.1@0,69.012 v1(0.77,69.012) ; v1(7.299,67.625) 7.299,68.384 C34.2@7.305,68.389 ; C36.2@10.075,56.8 10.225,56.95 10.225,57.061 v1(10.875,57.711)
  other v1: -7.4,69.062
M0: R11.1 R18.1 R102.2 XP1.9 | length 13
  Top Layer w0.2: XP1.9@15.77,12.63 18.547,9.853 22.917,9.853 23.324,9.446 23.324,9.359 23.677,9.006 R102.2@25.492,9.006 R11.1@27.267,9.006
M1: R10.1 R21.1 R101.2 XP1.7 | length 6.5
  Top Layer w0.2: XP1.7@15.77,10.09 16.857,9.003 R10.1@18.225,9.003 R101.2@20.033,9.003 R21.1@21.82,9.003
M2: R9.2 R20.1 R100.2 XP1.5 | length 10.3
  Top Layer w0.2: XP1.5@15.77,7.55 16.944,6.376 16.944,4.906 18.2,3.65 R9.2@18.225,3.65 R100.2@20.03,3.65 R20.1@21.821,3.65 ; R100.2@20.117,3.656 R20.1@21.9,3.656
MISO_1/PA11: DD5.45 XP9.13 XS5.5 | length 28.9
  Top Layer w0.2: XP9.13@-29.21,44.91 -27.473,44.91 -25.095,47.287 -24.303,47.287 XS5.5@-24.13,47.46 ; v1(-5.257,50.512) -5.257,50.62 -4.895,50.982 -4.895,51.65 -4.22,52.325 -4.22,52.675 DD5.45@-4.2,52.695
  Bottom Layer w0.2: XS5.5@-24.13,47.46 -22.264,47.46 -22.024,47.7 -17.961,47.7 -16.938,48.723 -14.876,48.723 -13.167,50.432 -5.574,50.432 -5.57,50.435 -5.333,50.435 v1(-5.257,50.512)
MK_N: DD14.3 XS1.A7 XS1.B7 | length 8.4
  Top Layer w0.2: DD14.3@-1.05,72.855 -0.655,72.46 -0.655,72.456 -0.5,72.301 1.249,72.301 1.854,72.906 1.854,73.952 1.476,74.33 0.975,74.33 0.796,74.51 0.796,75.28 0.7,75.375 0.7,75.92 0.49,76.13 0.01,76.13 -0.25,75.87 XS1.A7@-0.25,75.825
MK_P: DD14.1 XS1.A6 XS1.B6 | length 5.5
  Top Layer w0.2: XS1.B6@-0.75,75.23 -0.7,75.18 -0.7,74.54 -0.49,74.33 -0.01,74.33 0.2,74.54 ; XS1.A6@0.25,75.23 0.2,75.18 0.2,74.54 ; DD14.1@0.85,73.159 1.054,72.955 1.337,72.955 1.454,73.072 1.454,73.786 1.31,73.93 0.81,73.93 0.2,74.54
MK_USB_N: DD5.20 DD14.4 | length 11.7
  Top Layer w0.2: DD5.20@-3.4,62.505 -3.4,63.187 -4.525,64.312 -4.525,69.481 -3.705,70.301 -1.255,70.301 -1.255,70.349 -1.05,70.553 DD14.4@-1.05,70.911
MK_USB_P: DD5.19 DD14.6 | length 13.4
  Top Layer w0.2: DD5.19@-3,62.505 -3,63.352 -4.125,64.477 -4.125,69.315 -3.539,69.901 -0.767,69.901 -0.728,69.862 0.561,69.862 0.69,69.991 0.69,70.751 DD14.6@0.85,70.911
MOSI_1/PA10: DD5.46 R11.2 R119.2 XP9.15 | length 146.4
  Top Layer w0.2: v1(-34.75,23.703) -34.218,24.235 -34.218,28.56 ; XP9.15@-29.21,47.45 -29.4,47.26 -30.186,47.26 -31.246,46.2 -32.224,46.2 -34.218,44.207 -34.218,28.56 ; R119.2@-24.397,29.388 -27.481,29.388 -28.309,28.56 -34.218,28.56 ; v1(-5.041,49.628) -5.041,49.736 -4.79,49.987 -4.79,50.13 -4.495,50.425 -4.495,51.484 -3.994,51.985 -3.83,52.149 -3.82,52.159 -3.82,52.254 -3.82,52.335 -3.8,52.355 DD5.46@-3.8,52.695 ; v1(22.231,6.459) 26.296,6.459 27.242,7.406 R11.2@27.267,7.406
  Bottom Layer w0.2: v1(-34.75,23.703) -34.75,22.986 -34.35,22.586 -34.35,18.205 -28.767,12.622 -21.842,12.622 -18.941,9.722 -14.331,9.722 -13.927,10.125 -10.509,10.125 -7.422,13.213 -1.963,13.213 -1.352,13.824 2.406,13.824 2.712,14.13 16.82,14.13 17.809,13.141 17.809,10.881 v1(22.231,6.459) ; XP9.15@-29.21,47.44 -25.688,47.44 -24.45,48.678 -23.823,48.678 -23.469,48.324 cw(c-24.13,47.46) -23.305,48.169 ccw(c-23.154,48.3) -23.289,48.153 -23.232,48.1 -23.154,48.1 -18.132,48.1 -18.082,48.15 -18.076,48.15 -17.104,49.123 -15.042,49.123 -13.333,50.832 -5.933,50.832 -5.619,51.146 -5.042,51.146 -4.657,50.76 -4.657,50.176 -4.79,50.042 -4.79,49.945 -5.041,49.694 v1(-5.041,49.628)
NetC1_1: C1.1 R1.2 | length 1.8
  Top Layer w0.5: C1.1@-31.401,9.922 R1.2@-31.401,11.722
NetC1_2: C1.2 SB1.1 | length 2.9
  Top Layer w0.3: C1.2@-33.001,9.922 -32.779,9.701 -32.779,9.196 -31.858,8.274 -31.858,7.545 SB1.1@-31.813,7.5
NetC3_1: C3.1 C4.1 C5.2 L1.1 XS1.A4_B9 XS1.B4_A9 | length 27
  Top Layer w0.3: XS1.B4_A9@-2.4,75.28 -2.255,75.425 -2.255,76.045 -2.071,76.229 -2.071,76.343 v1@-2.014,76.401
  Top Layer w0.4: v1@-2.014,76.401 v1(-2.014,76.455)
  Top Layer w0.5: XS1.A4_B9@2.4,75.23 2.4,74.049 2.759,73.69 3.389,73.69 v1(3.408,73.671)
  Top Layer w0.6: v1(3.408,73.671) 3.569,73.831 6.973,73.831 8.17,75.029 C4.1@8.17,76.025 ; C4.1@8.188,76.025 10.349,76.025 10.7,76.376 10.7,77 10.85,77.15 12.159,77.15 13.225,76.084 14.159,76.084 L1.1@14.2,76.125 C3.1@14.2,77.825
  Bottom Layer w0.5: v1(-2.014,76.455) -1.337,77.132 1.398,77.132 1.9,76.63 1.9,75.179 v1(3.408,73.671)
NetC12_2: C12.2 DD5.28 L5.2 | length 8.6
  Top Layer w0.2: C12.2@-9.475,56.58 L5.2@-9.475,58.2 -9.3,58.375 v1(-9.3,58.891) ; v1(-8.642,60.657) -8.533,60.657 -8.23,60.353 -7.73,60.353 -7.577,60.2 -6.986,60.2 -6.586,59.8 DD5.28@-4.905,59.8
  Bottom Layer w0.2: v1(-9.3,58.891) -9.3,60.081 -8.725,60.657 v1(-8.642,60.657)
NetC16_2: C16.2 DD5.16 R45.2 | length 26.8
  Top Layer w0.2: v1(-2.053,66.099) -2.13,66.022 -2.13,65.671 -2.574,65.227 -2.574,64.623 -1.8,63.849 -1.8,63.815 -1.8,63.516 DD5.16@-1.8,62.505 ; v1(12.461,69.896) 12.513,69.896 13.318,70.7 R45.2@14.2,70.7
  Top Layer w0.3: C16.2@5.423,68.112 5.448,68.112 6.187,67.373 v1(6.203,67.373)
  Bottom Layer w0.2: v1(-2.053,66.099) -1.584,66.568 1.016,66.568 2.857,64.727 4.731,64.727 6.17,66.166 6.17,66.56 6.17,67.34 v1(6.203,67.373) ; v1@6.223,67.398 7.138,68.312 8.696,68.312 9.68,69.296 10.456,69.296 11.351,68.4 11.849,68.4 12.513,69.065 v1@12.513,69.896
NetC39_1: C39.1 L10.1 XS2.A4_B9 XS2.B4_A9 | length 10.9
  Top Layer w0.46: 2.4,7.936 v1@2.864,8.4
  Top Layer w0.5: XS2.A4_B9@-2.4,7.27 v1(-2.4,8.413) ; XS2.B4_A9@2.4,7.27 2.4,7.936 ; v1@2.864,8.4 2.894,8.4 v1(2.913,8.419) ; v1@2.898,8.434 3.022,8.557 3.286,8.821 3.286,9.404 3.382,9.5 L10.1@3.678,9.5
  Top Layer w0.6: L10.1@3.678,9.5 C39.1@5.2,9.5
  Bottom Layer w0.5: v1(-2.4,8.413) 2.907,8.413 v1(2.913,8.419)
NetC40_1: C40.1 R111.2 VT1.1 | length 4.1
  Top Layer w0.2: R111.2@-14.658,58.103 -14.633,58.103 -13.385,56.855 -13.241,56.855 -12.871,56.485 VT1.1@-12.871,54.89
NetC42_2: C42.2 DD7.2 Q1.1 | length 9
  Top Layer w0.2: DD7.2@5.738,24.05 5.788,24 6.529,24 6.867,23.662 6.867,23.641 7.275,23.233 7.275,18.875 8.067,18.083 8.067,17.95 C42.2@6.54,17.95
NetC43_2: C43.2 DD7.3 Q1.3 | length 7.6
  Top Layer w0.2: DD7.3@5.738,24.55 5.788,24.5 6.595,24.5 7.267,23.828 7.267,23.807 8.1,22.973 8.1,21.752 C43.2@8.098,21.75 ; C43.2@8.148,21.75 8.398,21.5 8.398,21.45 9.148,20.7 9.65,20.7 10.5,19.85 Q1.3@10.65,19.85
NetC59_2: C59.2 R99.1 XP6.7 | length 17.1
  Top Layer w0.2: XP6.7@-29.229,18.888 -28.354,18.013 -27.596,18.013 -26.684,18.925 -26.684,20.372 -23.51,23.546 -20.413,23.546 -20.254,23.705 -20.254,24.924 -19.176,26.001 R99.1@-19.176,26.026 -19.174,26.029 -19.174,27.803 C59.2@-19.171,27.805
NetC60_2: C60.2 R78.2 | length 1.8
  Top Layer w0.3: R78.2@-22.854,10.553 C60.2@-22.854,12.367
NetC63_2: C63.2 C64.2 C65.2 D1.1 DD12.2 FU1.2 R88.2 | length 32
  Top Layer w0.3: R88.2@16.974,43.7 C65.2@18.763,43.7 ; DD12.2@17.9,40 17.9,42.82 17.918,42.82 C65.2@18.768,43.67
  Top Layer w0.9: D1.1@15.682,63.06 15.682,62.667 15.682,60.069 21.201,54.55 21.201,53.222 C63.2@21.351,53.072 ; C65.2@18.763,43.7 C65.2@18.768,43.695 ; C65.2@18.768,43.67 C65.2@18.768,43.695 ; C63.2@21.325,53.046 C64.2@21.325,48.414 21.175,48.264 21.175,46.719 18.768,44.312 C65.2@18.768,43.695
  Top Layer w1: D1.1@15.682,63.06 15.882,62.86 18.707,62.86 FU1.2@18.9,62.667
NetC67_2: C67.2 DD12.4 | length 8.3
  Top Layer w0.3: C67.2@11.905,45.357 11.905,44.501 12.316,44.09 13.034,44.09 15.366,41.758 16.174,41.758 16.9,41.031 16.9,40.638 DD12.4@16.9,40
NetC68_1: C68.1 DD12.1 | length 2
  Top Layer w0.3: DD12.1@18.4,40 18.4,41.482 18.768,41.85 C68.1@18.768,41.875
NetC68_2: C68.2 D3.1 DD12.10 L14.1 | length 7.2
  Top Layer w0.3: v1(19.5,39.341) 19.5,40.982 20.068,41.55 20.068,41.575 C68.2@20.368,41.875
  Bottom Layer w0.3: v1(19.2,35.15) 19.2,35.176 19.5,35.476 v1(19.5,39.341)
NetC70_2: C70.2 R92.1 | length 1.9
  Top Layer w0.3: R92.1@14.7,30.2 16.3,30.2 C70.2@16.5,30
NetC71_2: C71.2 DD12.8 R92.2 | length 6
  Top Layer w0.3: R92.2@14.7,31.8 C71.2@16.5,31.8 16.5,33.064 17.4,33.964 DD12.8@17.4,35.6
NetC75_2: C75.2 DD7.21 | length 7.7
  Top Layer w0.2: DD7.21@1.75,33.038 1.75,31.845 2.245,31.35 3.85,31.35 4.276,31.776 C75.2@4.276,35.334
NetD2_1: D2.1 DD12.3 R88.1 R89.2 | length 9.5
  Top Layer w0.3: R88.1@15.374,43.7 14.55,43.7 13.825,44.425 R89.2@13.825,45.49 D2.1@15.974,45.49 ; R88.1@15.4,43.525 15.524,43.525 15.674,43.375 15.674,43.251 17.4,41.525 DD12.3@17.4,40
NetDD1_1: DD1.1 R4.2 R5.1 | length 9.4
  Top Layer w0.2: R4.2@-10.748,45.405 -10.748,43.705 -10.748,43.655 R5.1@-10.723,43.63 -5.703,43.63 -4.628,44.705 DD1.1@-3.6,44.705
NetDD1_2: DD1.2 R7.1 | length 7.8
  Top Layer w0.2: R7.1@-10.723,41.855 -6.307,41.855 -4.763,43.399 -3.636,43.399 DD1.2@-3.6,43.435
